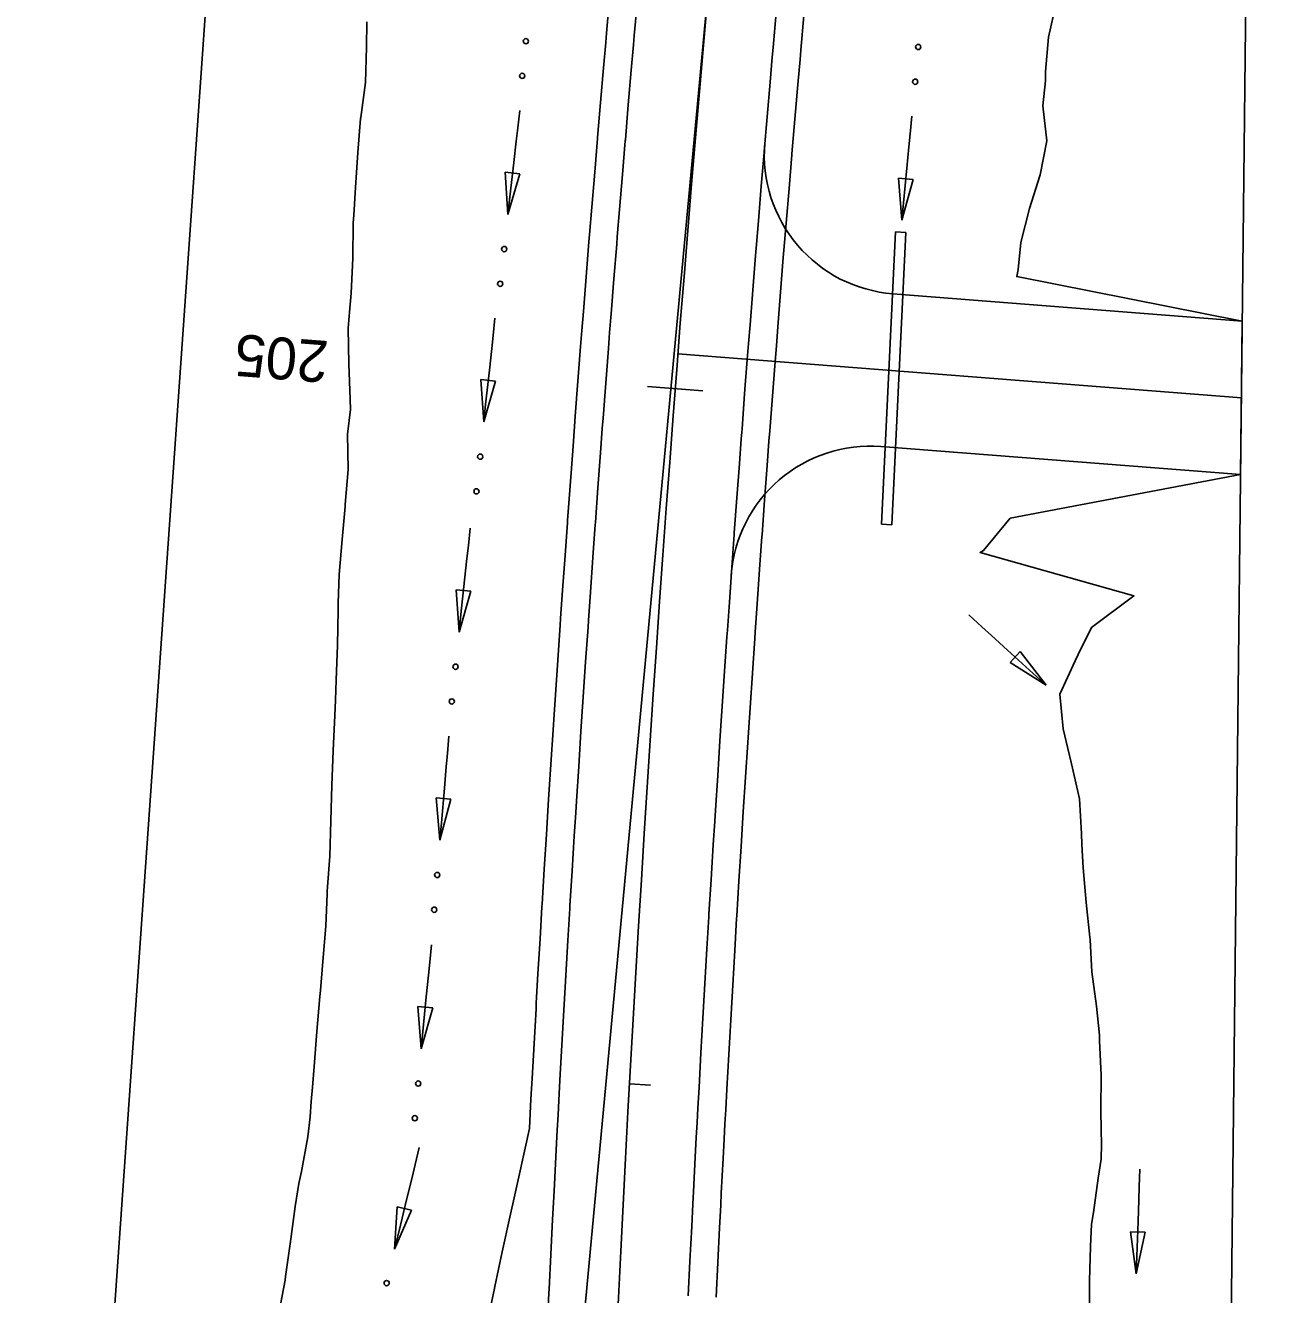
# Model space of a CAD drawing. Extents: x 1 to 1477871, y 1 to 1872901.
# Drawn here: x 1438531.3 to 1438712, y 1870306 to 1870488.2 of the extents above; entities that cross this region are included whole.
import ezdxf

# ---------------------------------------------------------------- set-up
doc = ezdxf.new("R2010")
doc.units = 0
for name, color, linetype in [('R_Drive', 7, 'Continuous'), ('R_Horz Alg', 7, 'Continuous'), ('R_Horz Alg Annot', 7, 'Continuous'), ('R_No Plot', 7, 'Continuous'), ('R_Proposed Const Limits_Cut', 7, 'Continuous'), ('R_Proposed Road_Lane', 7, 'Continuous'), ('R_Proposed Road_Shoulder', 7, 'Continuous'), ('R_ROW', 7, 'Continuous'), ('R_Water', 7, 'Continuous')]:
    doc.layers.add(name, color=color, linetype=linetype)

msp = doc.modelspace()

# ---------------------------------------------------------------- linework, layer by layer
at = {"layer": 'R_Drive'}
for p, q in [((1438706.04, 1870445.72), (1438655.87, 1870449.63)), ((1438705.79, 1870423.67), (1438706.04, 1870445.72)), ((1438705.79, 1870423.67), (1438654.15, 1870427.69))]:
    msp.add_line(p, q, dxfattribs=at)
for centre, start, end in [((1438657.42, 1870469.57), 175.2631, 265.55), ((1438652.6, 1870407.75), 85.55, 175.7589)]:
    msp.add_arc(centre, 20, start, end, dxfattribs=at)
at = {"layer": 'R_Horz Alg'}
msp.add_arc((1443194.86, 1870085.35), 4583.66, 174.66013, 180, dxfattribs=at)
at = {"layer": 'R_Horz Alg Annot'}
msp.add_line((1438611.19, 1870299.1), (1438631.09, 1870511.92), dxfattribs=at)
for points in [[(1438620.64, 1870436.32), (1438628.61, 1870435.7)], [(1438621.06, 1870336.06), (1438618.06, 1870336.23)]]:
    msp.add_lwpolyline(points, dxfattribs=at)
at = {"layer": 'R_No Plot'}
msp.add_line((1438705.92, 1870434.7), (1438625.01, 1870440.99), dxfattribs=at)
at = {"layer": 'R_Proposed Const Limits_Cut'}
for points in [[(1438684.12, 1870303.01), (1438684.12, 1870307.94), (1438684.26, 1870312.86), (1438684.41, 1870316.08), (1438684.66, 1870317.78), (1438685.36, 1870322.67), (1438685.76, 1870325.43), (1438685.85, 1870327.58), (1438685.77, 1870329.6), (1438685.75, 1870332.52), (1438685.77, 1870337.45), (1438685.56, 1870342.4), (1438685.52, 1870343.21), (1438685.12, 1870347.36), (1438684.44, 1870352.33), (1438684.19, 1870356.9), (1438684.17, 1870357.29), (1438683.64, 1870362.26), (1438683.18, 1870367.23), (1438683.03, 1870370.58), (1438682.96, 1870372.18), (1438682.65, 1870377.14), (1438681.53, 1870382.16), (1438681.01, 1870384.34), (1438680.33, 1870387.19), (1438679.87, 1870392.16), (1438682.03, 1870396.96), (1438682.48, 1870397.87), (1438684.39, 1870401.74), (1438690.48, 1870406.26), (1438668.39, 1870412.52), (1438668.9, 1870412.76), (1438672.74, 1870417.44), (1438705.79, 1870423.67), (1438706.04, 1870445.72), (1438673.66, 1870452.1), (1438673.85, 1870453.14), (1438674.26, 1870457.01), (1438675.5, 1870461.88), (1438676.96, 1870466.57), (1438677.01, 1870466.71), (1438678, 1870471.59), (1438677.43, 1870476.6), (1438677.8, 1870480.18), (1438677.81, 1870481.54), (1438678.24, 1870486.46), (1438679.32, 1870491.33)], [(1438567.78, 1870303.56), (1438568.62, 1870308.06), (1438568.7, 1870308.57), (1438569.38, 1870313.6), (1438570.05, 1870318.62), (1438570.61, 1870321.9), (1438570.99, 1870323.63), (1438571.88, 1870328.64), (1438572.22, 1870331.48), (1438572.36, 1870333.68), (1438572.54, 1870335.74), (1438572.78, 1870338.71), (1438573.2, 1870343.74), (1438573.62, 1870348.78), (1438573.69, 1870349.61), (1438574.05, 1870353.81), (1438574.48, 1870358.84), (1438574.65, 1870363.49), (1438574.64, 1870363.89), (1438575.06, 1870368.92), (1438575.19, 1870373.97), (1438575.27, 1870377.4), (1438575.31, 1870379.03), (1438575.52, 1870384.07), (1438575.75, 1870389.12), (1438575.84, 1870391.3), (1438575.97, 1870394.16), (1438576.15, 1870399.21), (1438576.23, 1870404.27), (1438576.25, 1870405.23), (1438576.39, 1870409.32), (1438576.82, 1870414.35), (1438577.23, 1870419.11), (1438577.26, 1870419.38), (1438577.69, 1870424.42), (1438577.56, 1870429.49), (1438578.03, 1870433.01), (1438577.97, 1870434.52), (1438577.78, 1870439.6), (1438577.7, 1870444.68), (1438577.88, 1870446.98), (1438578.1, 1870449.71), (1438578.35, 1870454.76), (1438578.41, 1870459.82), (1438578.48, 1870460.9), (1438578.73, 1870464.87), (1438579.07, 1870469.91), (1438579.47, 1870474.79), (1438579.49, 1870474.94), (1438580.16, 1870479.96), (1438580.3, 1870485.02), (1438580.37, 1870488.69)]]:
    msp.add_lwpolyline(points, dxfattribs=at)
at = {"layer": 'R_Proposed Road_Lane'}
for points in [[(1438606.29, 1870301.74), (1438606.51, 1870306.23), (1438606.53, 1870306.75), (1438606.78, 1870311.75), (1438607.03, 1870316.76), (1438607.19, 1870320.03), (1438607.28, 1870321.76), (1438607.54, 1870326.77), (1438607.69, 1870329.59), (1438607.81, 1870331.77), (1438607.92, 1870333.82), (1438608.08, 1870336.78), (1438608.36, 1870341.78), (1438608.64, 1870346.78), (1438608.69, 1870347.61), (1438608.93, 1870351.78), (1438609.22, 1870356.79), (1438609.5, 1870361.39), (1438609.52, 1870361.79), (1438609.82, 1870366.79), (1438610.13, 1870371.79), (1438610.35, 1870375.18), (1438610.45, 1870376.79), (1438610.77, 1870381.79), (1438611.09, 1870386.79), (1438611.24, 1870388.96), (1438611.43, 1870391.79), (1438611.76, 1870396.79), (1438612.11, 1870401.79), (1438612.17, 1870402.74), (1438612.45, 1870406.79), (1438612.81, 1870411.79), (1438613.15, 1870416.51), (1438613.17, 1870416.79), (1438613.53, 1870421.78), (1438613.9, 1870426.78), (1438614.16, 1870430.29), (1438614.28, 1870431.78), (1438614.66, 1870436.78), (1438615.04, 1870441.77), (1438615.22, 1870444.06), (1438615.43, 1870446.77), (1438615.83, 1870451.76), (1438616.23, 1870456.76), (1438616.32, 1870457.82), (1438616.64, 1870461.75), (1438617.05, 1870466.74), (1438617.46, 1870471.59), (1438617.47, 1870471.74), (1438617.9, 1870476.73), (1438618.33, 1870481.72), (1438618.64, 1870485.35), (1438618.76, 1870486.72), (1438619.2, 1870491.71)], [(1438626.51, 1870305.79), (1438626.75, 1870310.77), (1438627, 1870315.75), (1438627.17, 1870319.01), (1438627.26, 1870320.73), (1438627.51, 1870325.72), (1438627.66, 1870328.53), (1438627.78, 1870330.7), (1438627.89, 1870332.74), (1438628.05, 1870335.68), (1438628.32, 1870340.66), (1438628.61, 1870345.64), (1438628.65, 1870346.47), (1438628.89, 1870350.62), (1438629.19, 1870355.6), (1438629.46, 1870360.19), (1438629.48, 1870360.58), (1438629.79, 1870365.56), (1438630.09, 1870370.54), (1438630.31, 1870373.92), (1438630.41, 1870375.52), (1438630.73, 1870380.5), (1438631.05, 1870385.48), (1438631.19, 1870387.64), (1438631.38, 1870390.46), (1438631.72, 1870395.44), (1438632.06, 1870400.41), (1438632.12, 1870401.36), (1438632.41, 1870405.39), (1438632.76, 1870410.37), (1438633.09, 1870415.07), (1438633.11, 1870415.34), (1438633.48, 1870420.32), (1438633.84, 1870425.29), (1438634.11, 1870428.79), (1438634.22, 1870430.27), (1438634.6, 1870435.25), (1438634.98, 1870440.22), (1438635.16, 1870442.5), (1438635.37, 1870445.19), (1438635.77, 1870450.17), (1438636.17, 1870455.14), (1438636.25, 1870456.2), (1438636.57, 1870460.11), (1438636.99, 1870465.08), (1438637.39, 1870469.91), (1438637.4, 1870470.05), (1438637.82, 1870475.03), (1438638.25, 1870480), (1438638.57, 1870483.6), (1438638.69, 1870484.97), (1438639.12, 1870489.94)]]:
    msp.add_lwpolyline(points, dxfattribs=at)
at = {"layer": 'R_Proposed Road_Shoulder'}
for points in [[(1438597.67, 1870302.15), (1438598.63, 1870306.61), (1438598.74, 1870307.12), (1438599.81, 1870312.1), (1438600.9, 1870317.07), (1438601.61, 1870320.31), (1438601.99, 1870322.04), (1438603.08, 1870327), (1438603.7, 1870329.8), (1438603.81, 1870331.99), (1438603.92, 1870334.03), (1438604.08, 1870336.99), (1438604.36, 1870342), (1438604.65, 1870347.01), (1438604.69, 1870347.83), (1438604.93, 1870352.02), (1438605.23, 1870357.02), (1438605.5, 1870361.63), (1438605.53, 1870362.03), (1438605.83, 1870367.03), (1438606.14, 1870372.04), (1438606.35, 1870375.43), (1438606.46, 1870377.04), (1438606.78, 1870382.05), (1438607.1, 1870387.05), (1438607.25, 1870389.22), (1438607.44, 1870392.06), (1438607.77, 1870397.06), (1438608.11, 1870402.07), (1438608.18, 1870403.01), (1438608.46, 1870407.07), (1438608.82, 1870412.07), (1438609.16, 1870416.8), (1438609.18, 1870417.07), (1438609.54, 1870422.08), (1438609.91, 1870427.08), (1438610.17, 1870430.59), (1438610.29, 1870432.08), (1438610.67, 1870437.08), (1438611.05, 1870442.08), (1438611.23, 1870444.37), (1438611.45, 1870447.08), (1438611.84, 1870452.08), (1438612.25, 1870457.08), (1438612.33, 1870458.15), (1438612.65, 1870462.08), (1438613.07, 1870467.08), (1438613.47, 1870471.92), (1438613.49, 1870472.07), (1438613.91, 1870477.07), (1438614.34, 1870482.07), (1438614.66, 1870485.69), (1438614.78, 1870487.06), (1438615.22, 1870492.06)], [(1438630.5, 1870305.59), (1438630.75, 1870310.57), (1438631, 1870315.55), (1438631.16, 1870318.8), (1438631.25, 1870320.53), (1438631.51, 1870325.51), (1438631.66, 1870328.31), (1438631.77, 1870330.48), (1438631.88, 1870332.52), (1438632.04, 1870335.46), (1438632.32, 1870340.44), (1438632.6, 1870345.42), (1438632.65, 1870346.24), (1438632.89, 1870350.39), (1438633.18, 1870355.37), (1438633.45, 1870359.95), (1438633.48, 1870360.34), (1438633.78, 1870365.32), (1438634.09, 1870370.29), (1438634.3, 1870373.66), (1438634.4, 1870375.27), (1438634.72, 1870380.24), (1438635.04, 1870385.22), (1438635.19, 1870387.37), (1438635.37, 1870390.19), (1438635.71, 1870395.17), (1438636.05, 1870400.14), (1438636.11, 1870401.08), (1438636.4, 1870405.11), (1438636.75, 1870410.08), (1438637.08, 1870414.78), (1438637.1, 1870415.05), (1438637.47, 1870420.03), (1438637.83, 1870425), (1438638.09, 1870428.49), (1438638.21, 1870429.97), (1438638.58, 1870434.94), (1438638.97, 1870439.91), (1438639.15, 1870442.18), (1438639.36, 1870444.88), (1438639.75, 1870449.85), (1438640.15, 1870454.82), (1438640.24, 1870455.88), (1438640.56, 1870459.78), (1438640.97, 1870464.75), (1438641.38, 1870469.57), (1438641.39, 1870469.72), (1438641.81, 1870474.69), (1438642.24, 1870479.65), (1438642.55, 1870483.26), (1438642.67, 1870484.62), (1438643.11, 1870489.58)]]:
    msp.add_lwpolyline(points, dxfattribs=at)
at = {"layer": 'R_ROW'}
for p, q in [((1438531.34, 1870121.98), (1438591.99, 1870985.89)), ((1438711.98, 1870984.32), (1438701.19, 1870006.35))]:
    msp.add_line(p, q, dxfattribs=at)
at = {"layer": 'R_Water'}
for p, q in [((1438602.34, 1870466.87), (1438600.24, 1870467.11)), ((1438600.24, 1870467.11), (1438600.61, 1870461.03)), ((1438600.61, 1870461.03), (1438602.34, 1870466.87)), ((1438658.81, 1870466.05), (1438656.7, 1870466.25)), ((1438656.7, 1870466.25), (1438657.18, 1870460.18)), ((1438657.18, 1870460.18), (1438658.81, 1870466.05)), ((1438656.25, 1870458.52), (1438654.25, 1870416.56)), ((1438657.74, 1870458.44), (1438655.75, 1870416.49)), ((1438656.25, 1870458.52), (1438657.74, 1870458.44)), ((1438598.84, 1870437.08), (1438596.74, 1870437.31)), ((1438596.74, 1870437.31), (1438597.14, 1870431.23)), ((1438597.14, 1870431.23), (1438598.84, 1870437.08)), ((1438654.25, 1870416.56), (1438655.75, 1870416.49)), ((1438595.29, 1870406.93), (1438593.19, 1870407.16)), ((1438593.19, 1870407.16), (1438593.6, 1870401.08)), ((1438593.6, 1870401.08), (1438595.29, 1870406.93)), ((1438674.16, 1870398.27), (1438672.73, 1870396.7)), ((1438677.89, 1870393.45), (1438674.16, 1870398.27)), ((1438672.73, 1870396.7), (1438677.89, 1870393.45)), ((1438592.43, 1870377.09), (1438590.32, 1870377.27)), ((1438590.32, 1870377.27), (1438590.86, 1870371.2)), ((1438590.86, 1870371.2), (1438592.43, 1870377.09)), ((1438589.81, 1870347.13), (1438587.7, 1870347.33)), ((1438587.7, 1870347.33), (1438588.18, 1870341.26)), ((1438588.18, 1870341.26), (1438589.81, 1870347.13)), ((1438584.73, 1870318.58), (1438584.35, 1870312.5)), ((1438584.35, 1870312.5), (1438586.79, 1870318.09)), ((1438586.79, 1870318.09), (1438584.73, 1870318.58)), ((1438692.09, 1870314.93), (1438689.97, 1870315)), ((1438689.97, 1870315), (1438690.81, 1870308.97)), ((1438690.81, 1870308.97), (1438692.09, 1870314.93))]:
    msp.add_line(p, q, dxfattribs=at)
for points in [[(1438602.3, 1870475.93), (1438602.02, 1870473.43), (1438601.81, 1870471.56), (1438601.46, 1870468.48), (1438600.9, 1870463.53), (1438600.61, 1870461.03)], [(1438658.61, 1870475.11), (1438658.37, 1870472.6), (1438658.19, 1870470.73), (1438657.9, 1870467.64), (1438657.42, 1870462.68), (1438657.18, 1870460.18)], [(1438598.75, 1870446.14), (1438598.48, 1870443.64), (1438598.28, 1870441.77), (1438597.95, 1870438.68), (1438597.41, 1870433.73), (1438597.14, 1870431.23)], [(1438595.2, 1870415.99), (1438594.93, 1870413.49), (1438594.73, 1870411.62), (1438594.4, 1870408.53), (1438593.87, 1870403.58), (1438593.59, 1870401.08)], [(1438666.78, 1870403.53), (1438668.64, 1870401.84), (1438670.04, 1870400.57), (1438672.34, 1870398.49), (1438676.03, 1870395.14), (1438677.89, 1870393.45)], [(1438592.15, 1870386.15), (1438591.93, 1870383.64), (1438591.77, 1870381.76), (1438591.51, 1870378.67), (1438591.08, 1870373.71), (1438590.86, 1870371.2)], [(1438589.62, 1870356.19), (1438589.38, 1870353.68), (1438589.2, 1870351.81), (1438588.9, 1870348.72), (1438588.42, 1870343.76), (1438588.18, 1870341.26)], [(1438587.88, 1870327.08), (1438587.29, 1870324.63), (1438586.85, 1870322.8), (1438586.11, 1870319.79), (1438584.94, 1870314.95), (1438584.35, 1870312.5)], [(1438691.35, 1870323.96), (1438691.26, 1870321.44), (1438691.2, 1870319.56), (1438691.08, 1870316.46), (1438690.9, 1870311.48), (1438690.81, 1870308.97)]]:
    msp.add_lwpolyline(points, dxfattribs=at)
for centre in [(1438603.19, 1870485.89), (1438659.52, 1870485.06), (1438602.67, 1870480.91), (1438659.09, 1870480.07), (1438600.08, 1870456.05), (1438599.51, 1870451.07), (1438596.64, 1870426.25), (1438596.1, 1870421.27), (1438593.09, 1870396.1), (1438592.55, 1870391.12), (1438590.46, 1870366.21), (1438590.03, 1870361.22), (1438587.73, 1870336.27), (1438587.25, 1870331.29), (1438583.2, 1870307.63)]:
    msp.add_circle(centre, 0.375, dxfattribs=at)

# ---------------------------------------------------------------- texts
at = {"layer": 'R_Horz Alg Annot'}
msp.add_text('205', height=6, rotation=175.6125, dxfattribs=at).set_placement((1438575, 1870442.83))

doc.saveas('drawing.dxf')
